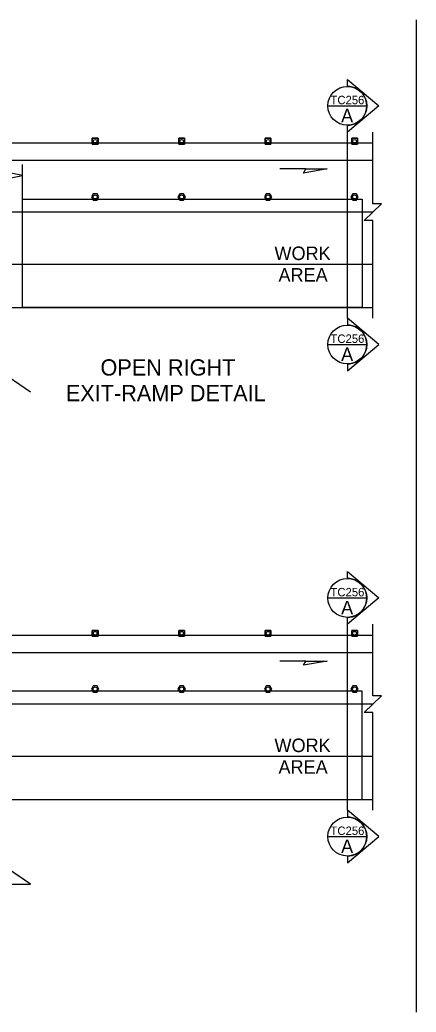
# Model space of a CAD drawing. Extents: x 99999 to 100116, y 99995 to 100013.
# Drawn here: x 100044.94 to 100047.88, y 100001.58 to 100008.92 of the extents above; entities that cross this region are included whole.
import ezdxf

# ---------------------------------------------------------------- set-up
doc = ezdxf.new("R2010")
doc.units = 0
for name, color, linetype in [('RD_MK_LineEdgeYellow', 7, 'Continuous'), ('RD_MK_LineLane', 7, 'Continuous'), ('SH_DE_DetailHeading2Text', 7, 'Continuous'), ('SH_GI_SectionCut', 7, 'Continuous'), ('TR_WZ_TallChanDevice', 7, 'Continuous'), ('TR_WZ_TrafficCone', 7, 'Continuous'), ('TR_WZ_WorkAreaLabel', 7, 'Continuous'), ('TR_WZ_WorkZoneDetails', 7, 'Continuous')]:
    doc.layers.add(name, color=color, linetype=linetype)

msp = doc.modelspace()

# ---------------------------------------------------------------- linework, layer by layer
at = {"layer": 'RD_MK_LineEdgeYellow'}
for p, q in [((100040.32, 100007.8789), (100047.555, 100007.8789)), ((100044.0968, 100007.1109), (100047.555, 100007.1109)), ((100040.32, 100004.238), (100047.555, 100004.238)), ((100044.0968, 100003.47), (100047.555, 100003.47))]:
    msp.add_line(p, q, dxfattribs=at)
at = {"layer": 'RD_MK_LineLane'}
for points in [[(100047.555, 100007.4949), (100040.32, 100007.4949)], [(100047.555, 100003.854), (100040.32, 100003.854)]]:
    msp.add_lwpolyline(points, dxfattribs=at)
at = {"layer": 'SH_GI_SectionCut'}
for p, q in [((100047.3657, 100008.4258), (100047.3657, 100008.4767)), ((100047.3657, 100008.4767), (100047.5983, 100008.2818)), ((100047.5983, 100008.2818), (100047.3657, 100008.0869)), ((100047.3657, 100008.0869), (100047.3657, 100008.1378)), ((100047.3657, 100006.7109), (100047.3657, 100008.0869)), ((100047.3657, 100006.7109), (100047.3657, 100006.66)), ((100047.5983, 100006.516), (100047.3657, 100006.7109)), ((100047.3657, 100006.3211), (100047.5983, 100006.516)), ((100047.3657, 100006.372), (100047.3657, 100006.3211)), ((100047.3657, 100004.7848), (100047.3657, 100004.8357)), ((100047.3657, 100004.8357), (100047.5983, 100004.6408)), ((100047.5983, 100004.6408), (100047.3657, 100004.446)), ((100047.3657, 100004.446), (100047.3657, 100004.4968)), ((100047.3657, 100003.0699), (100047.3657, 100004.446)), ((100047.3657, 100003.07), (100047.3657, 100003.0191)), ((100047.5983, 100002.8751), (100047.3657, 100003.07)), ((100047.3657, 100002.6802), (100047.5983, 100002.8751)), ((100047.3657, 100002.7311), (100047.3657, 100002.6802))]:
    msp.add_line(p, q, dxfattribs=at)
for points in [[(100047.2217, 100008.2818), (100047.5097, 100008.2818)], [(100047.2217, 100006.516), (100047.5097, 100006.516)], [(100047.2217, 100004.6408), (100047.5097, 100004.6408)], [(100047.2217, 100002.8751), (100047.5097, 100002.8751)]]:
    msp.add_lwpolyline(points, dxfattribs=at)
for centre in [(100047.3657, 100008.2818), (100047.3657, 100006.516), (100047.3657, 100004.6408), (100047.3657, 100002.8751)]:
    msp.add_circle(centre, 0.144, dxfattribs=at)
for centre in [(100047.3657, 100008.2818), (100047.3657, 100006.516), (100047.3657, 100004.6408), (100047.3657, 100002.8751)]:
    msp.add_arc(centre, 0.144, 269.99779, 90.00221, dxfattribs=at)
at = {"layer": 'TR_WZ_TallChanDevice'}
for points in [[(100045.5128, 100007.6319), (100045.4851, 100007.6319), (100045.4712, 100007.6079), (100045.4851, 100007.5839), (100045.5128, 100007.5839), (100045.5266, 100007.6079)], [(100046.1528, 100007.6319), (100046.1251, 100007.6319), (100046.1112, 100007.6079), (100046.1251, 100007.5839), (100046.1528, 100007.5839), (100046.1666, 100007.6079)], [(100046.7928, 100007.6319), (100046.7651, 100007.6319), (100046.7512, 100007.6079), (100046.7651, 100007.5839), (100046.7928, 100007.5839), (100046.8066, 100007.6079)], [(100047.4328, 100007.6319), (100047.4051, 100007.6319), (100047.3912, 100007.6079), (100047.4051, 100007.5839), (100047.4328, 100007.5839), (100047.4466, 100007.6079)], [(100045.5128, 100003.9909), (100045.4851, 100003.9909), (100045.4712, 100003.9669), (100045.4851, 100003.9429), (100045.5128, 100003.9429), (100045.5266, 100003.9669)], [(100046.1528, 100003.9909), (100046.1251, 100003.9909), (100046.1112, 100003.9669), (100046.1251, 100003.9429), (100046.1528, 100003.9429), (100046.1666, 100003.9669)], [(100046.7928, 100003.9909), (100046.7651, 100003.9909), (100046.7512, 100003.9669), (100046.7651, 100003.9429), (100046.7928, 100003.9429), (100046.8066, 100003.9669)], [(100047.4328, 100003.9909), (100047.4051, 100003.9909), (100047.3912, 100003.9669), (100047.4051, 100003.9429), (100047.4328, 100003.9429), (100047.4466, 100003.9669)]]:
    msp.add_lwpolyline(points, close=True, dxfattribs=at)
for points in [[(100045.5128, 100007.6319), (100045.4851, 100007.6319), (100045.4712, 100007.6079), (100045.4851, 100007.5839), (100045.5128, 100007.5839), (100045.5266, 100007.6079), (100045.5128, 100007.6319)], [(100046.1528, 100007.6319), (100046.1251, 100007.6319), (100046.1112, 100007.6079), (100046.1251, 100007.5839), (100046.1528, 100007.5839), (100046.1666, 100007.6079), (100046.1528, 100007.6319)], [(100046.7928, 100007.6319), (100046.7651, 100007.6319), (100046.7512, 100007.6079), (100046.7651, 100007.5839), (100046.7928, 100007.5839), (100046.8066, 100007.6079), (100046.7928, 100007.6319)], [(100047.4328, 100007.6319), (100047.4051, 100007.6319), (100047.3912, 100007.6079), (100047.4051, 100007.5839), (100047.4328, 100007.5839), (100047.4466, 100007.6079), (100047.4328, 100007.6319)], [(100045.5128, 100003.9909), (100045.4851, 100003.9909), (100045.4712, 100003.9669), (100045.4851, 100003.9429), (100045.5128, 100003.9429), (100045.5266, 100003.9669), (100045.5128, 100003.9909)], [(100046.1528, 100003.9909), (100046.1251, 100003.9909), (100046.1112, 100003.9669), (100046.1251, 100003.9429), (100046.1528, 100003.9429), (100046.1666, 100003.9669), (100046.1528, 100003.9909)], [(100046.7928, 100003.9909), (100046.7651, 100003.9909), (100046.7512, 100003.9669), (100046.7651, 100003.9429), (100046.7928, 100003.9429), (100046.8066, 100003.9669), (100046.7928, 100003.9909)], [(100047.4328, 100003.9909), (100047.4051, 100003.9909), (100047.3912, 100003.9669), (100047.4051, 100003.9429), (100047.4328, 100003.9429), (100047.4466, 100003.9669), (100047.4328, 100003.9909)]]:
    msp.add_lwpolyline(points, dxfattribs=at)
for centre in [(100045.4989, 100007.6079), (100046.1389, 100007.6079), (100046.7789, 100007.6079), (100047.4189, 100007.6079), (100045.4989, 100003.9669), (100046.1389, 100003.9669), (100046.7789, 100003.9669), (100047.4189, 100003.9669)]:
    msp.add_circle(centre, 0.015, dxfattribs=at)
at = {"layer": 'TR_WZ_TrafficCone'}
for points in [[(100045.4776, 100008.0416), (100045.5203, 100008.0416), (100045.5203, 100007.9989), (100045.4776, 100007.9989), (100045.4776, 100008.0416)], [(100045.4776, 100007.9989), (100045.5203, 100007.9989), (100045.5203, 100008.0416), (100045.4776, 100008.0416), (100045.4776, 100007.9989)], [(100046.1176, 100008.0416), (100046.1603, 100008.0416), (100046.1603, 100007.9989), (100046.1176, 100007.9989), (100046.1176, 100008.0416)], [(100046.1176, 100007.9989), (100046.1603, 100007.9989), (100046.1603, 100008.0416), (100046.1176, 100008.0416), (100046.1176, 100007.9989)], [(100046.7576, 100008.0416), (100046.8003, 100008.0416), (100046.8003, 100007.9989), (100046.7576, 100007.9989), (100046.7576, 100008.0416)], [(100046.7576, 100007.9989), (100046.8003, 100007.9989), (100046.8003, 100008.0416), (100046.7576, 100008.0416), (100046.7576, 100007.9989)], [(100047.3976, 100008.0416), (100047.4403, 100008.0416), (100047.4403, 100007.9989), (100047.3976, 100007.9989), (100047.3976, 100008.0416)], [(100047.3976, 100007.9989), (100047.4403, 100007.9989), (100047.4403, 100008.0416), (100047.3976, 100008.0416), (100047.3976, 100007.9989)], [(100045.4776, 100004.4006), (100045.5203, 100004.4006), (100045.5203, 100004.358), (100045.4776, 100004.358), (100045.4776, 100004.4006)], [(100045.4776, 100004.358), (100045.5203, 100004.358), (100045.5203, 100004.4006), (100045.4776, 100004.4006), (100045.4776, 100004.358)], [(100046.1176, 100004.4006), (100046.1603, 100004.4006), (100046.1603, 100004.358), (100046.1176, 100004.358), (100046.1176, 100004.4006)], [(100046.1176, 100004.358), (100046.1603, 100004.358), (100046.1603, 100004.4006), (100046.1176, 100004.4006), (100046.1176, 100004.358)], [(100046.7576, 100004.4006), (100046.8003, 100004.4006), (100046.8003, 100004.358), (100046.7576, 100004.358), (100046.7576, 100004.4006)], [(100046.7576, 100004.358), (100046.8003, 100004.358), (100046.8003, 100004.4006), (100046.7576, 100004.4006), (100046.7576, 100004.358)], [(100047.3976, 100004.4006), (100047.4403, 100004.4006), (100047.4403, 100004.358), (100047.3976, 100004.358), (100047.3976, 100004.4006)], [(100047.3976, 100004.358), (100047.4403, 100004.358), (100047.4403, 100004.4006), (100047.3976, 100004.4006), (100047.3976, 100004.358)]]:
    msp.add_lwpolyline(points, dxfattribs=at)
for centre in [(100045.4989, 100008.0202), (100046.1389, 100008.0202), (100046.7789, 100008.0202), (100047.4189, 100008.0202), (100045.4989, 100004.3793), (100046.1389, 100004.3793), (100046.7789, 100004.3793), (100047.4189, 100004.3793)]:
    msp.add_circle(centre, 0.0133, dxfattribs=at)
at = {"layer": 'TR_WZ_WorkZoneDetails'}
for p, q in [((100047.875, 100008.9181), (100047.875, 100001.5759)), ((100040.32, 100008.0069), (100047.555, 100008.0069)), ((100040.32, 100008.0069), (100047.555, 100008.0069)), ((100044.9608, 100007.5909), (100044.9608, 100007.8473)), ((100047.0586, 100007.8149), (100046.8658, 100007.8149)), ((100045.0213, 100006.1639), (100044.0968, 100006.7909)), ((100044.0968, 100006.7909), (100047.555, 100006.7909)), ((100040.32, 100004.366), (100047.555, 100004.366)), ((100047.0586, 100004.174), (100046.8658, 100004.174)), ((100045.0213, 100002.523), (100044.0968, 100003.15)), ((100044.0968, 100003.15), (100047.555, 100003.15))]:
    msp.add_line(p, q, dxfattribs=at)
for points in [[(100047.555, 100006.7109), (100047.555, 100007.433), (100047.491, 100007.433), (100047.619, 100007.5569), (100047.555, 100007.5569), (100047.555, 100008.0869)], [(100047.555, 100003.07), (100047.555, 100003.792), (100047.491, 100003.792), (100047.619, 100003.9159), (100047.555, 100003.9159), (100047.555, 100004.446)]]:
    msp.add_lwpolyline(points, dxfattribs=at)
for points in [[(100047.2159, 100007.8149), (100047.0408, 100007.7841), (100047.0586, 100007.8149)], [(100044.9608, 100007.7659), (100044.8625, 100007.7851), (100044.867, 100007.7659), (100044.8625, 100007.7466)], [(100044.9608, 100006.7909), (100044.9608, 100007.5909), (100047.475, 100007.5909), (100047.475, 100006.7909)], [(100047.2159, 100004.174), (100047.0408, 100004.1431), (100047.0586, 100004.174)], [(100040.4, 100003.15), (100042.6438, 100003.15), (100043.5728, 100002.523), (100045.0213, 100002.523), (100044.0968, 100003.15), (100045.8504, 100003.15), (100047.475, 100003.15), (100047.475, 100003.95), (100040.4, 100003.95)]]:
    msp.add_lwpolyline(points, close=True, dxfattribs=at)

# ---------------------------------------------------------------- texts
at = {"layer": 'SH_DE_DetailHeading2Text'}
for s, p in [('OPEN RIGHT', (100045.5382, 100006.2863)), ('EXIT-RAMP DETAIL', (100045.2814, 100006.0963))]:
    msp.add_text(s, height=0.12, rotation=360, dxfattribs=at).set_placement(p)
at = {"layer": 'SH_GI_SectionCut'}
for p in [(100047.2408, 100008.2934), (100047.2408, 100006.5276), (100047.2408, 100004.6524), (100047.2408, 100002.8867)]:
    msp.add_text('TC256', height=0.0625, dxfattribs=at).set_placement(p)
for p in [(100047.3195, 100008.1598), (100047.3195, 100006.394), (100047.3195, 100004.5188), (100047.3195, 100002.7531)]:
    msp.add_text('A', height=0.1, rotation=359.99005, dxfattribs=at).set_placement(p)
at = {"layer": 'TR_WZ_WorkAreaLabel'}
for s, p in [('WORK', (100046.8263, 100007.1409)), ('AREA', (100046.8559, 100006.9809)), ('WORK', (100046.8263, 100003.5)), ('AREA', (100046.8559, 100003.34))]:
    msp.add_text(s, height=0.1, dxfattribs=at).set_placement(p)

doc.saveas('drawing.dxf')
